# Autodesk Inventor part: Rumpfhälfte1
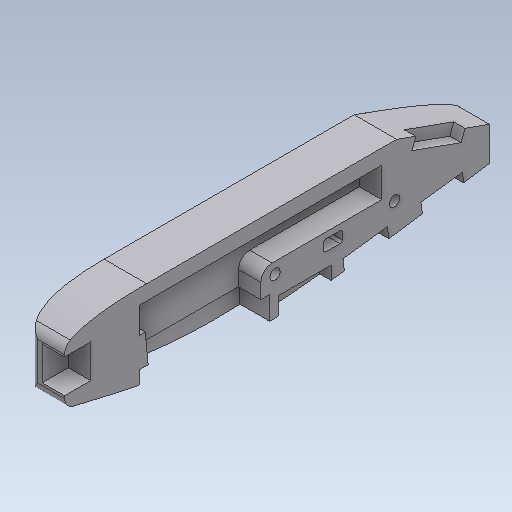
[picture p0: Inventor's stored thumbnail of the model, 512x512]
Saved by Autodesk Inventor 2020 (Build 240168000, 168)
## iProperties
Part Number: Rumpfhälfte1
Material: GEDA Polyamid schwarz
Document SubType Name: Modeling
Designer: Admin
Mass: 2170.29 g
Surface Area: 2080.02 cm^2
Volume: 1903.76 cm^3
Density: 1.14 g/cm^3
Appearance: GEDA Plastik schwarz A
Gewicht: 2,170 kg
G_L: 0
G_H: 0
G_B: 0
InventorVersion: 2019.4
VAULT_Status: in Bearbeitung
Revision: -
Max. Breite: 0
Max. Höhe: 0
Max. Länge: 0
Max. Abmessungen: 0 x 0 x 0
Author: Admin
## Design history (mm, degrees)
derived "RUMPFHÄLFTE_RUMPFHÄLFTE--IPT.ipt"
  sketch "Skizze1"
    geometry: L1 (0, 285)-(57, 285) reference; L2 (57, 285)-(57, -285) reference; L3 (57, -285)-(0, -285) reference; L4 (0, -285)-(0, 285) reference; L5 (40, 285)-(57, 285) reference; L6 (57, 285)-(57, 175) reference; L7 (36, -285)-(57, -285) reference; L8 (57, -285)-(57, -175) reference; 2 further points
  sketch "Skizze2"
    geometry: L1 (90, 0)-(139.333, 200) reference; L2 (139.333, 200)-(139.333, 250) reference; L3 (139.333, 250)-(90, 570) reference; L4 (0, 570)-(0, 0) reference; L5 (90, 0)-(137, 0) reference; L6 (137, 0)-(137, 570) reference; L7 (137, 570)-(90, 570) reference; L8 (45, 570)-(0, 445) reference; L9 (0, 570)-(0, 0) reference; L10 (20, 0)-(0, 20) reference; L11 (0, 20)-(0, 110) reference; L12 (46.491, 0)-(-10, 0) reference; L13 (-10, 0)-(-10, 570) reference; L14 (-10, 570)-(45, 570) reference; L15 (0, 110)-(0, 445) reference; L16 (0, 0)-(127, 0) reference; 7 further points
    constraints: 2 other
  sketch "Skizze3"
    geometry: L1 (27.484, -110)-(78.236, -110) reference; L2 (75, -110)-(30, -110) reference; L3 (30, -110)-(30, -75) reference; L4 (30, -75)-(75, -75) reference; L5 (75, -75)-(75, -110) reference; L6 (0, 335)-(0, 0) reference; L7 (0, 335)-(44.762, 459.339) reference; L8 (23.31, 355.465)-(47.02, 421.327) reference; L9 (32.907, 426.408)-(47.02, 421.327) reference; L10 (23.31, 355.465)-(9.196, 360.546) reference; L11 (5.4, 350)-(0, 335) reference; L12 (9.196, 360.546)-(32.907, 426.408) reference; L13 (127, -10)-(20, -10) reference; L14 (20, -10)-(20, 165) reference; L15 (127, 165)-(127, -10) reference; L16 (20, 165)-(60, 165) reference; L17 (60, 165)-(60, 315) reference; L18 (20, 315)-(20, 165) reference; L19 (127, 177)-(102, 177) reference; L20 (102, 177)-(102, 247) reference; L21 (102, 247)-(127, 247) reference; L22 (127, 247)-(127, 177) reference; L23 (45.703, 460)-(89.142, 460) reference; L24 (60, 315)-(20, 315) reference; L25 (95, -10)-(55, -10) reference; L26 (55, -10)-(55, -2) reference; L27 (55, -2)-(95, 2) reference; L28 (95, 2)-(95, -10) reference; L29 (60, 165)-(60, 153) reference; L30 (60, 153)-(95, 153) reference; L31 (95, 153)-(95, 165) reference; L32 (20, 165)-(60, 165) reference; L33 (95, 165)-(127, 165) reference; L34 (117.65, 264.922)-(102.65, 263) reference; L35 (102.65, 263)-(95.026, 322.514) reference; L36 (95.026, 322.514)-(110.026, 324.435) reference; L37 (103.659, 369.358)-(89.261, 367.514) reference; L38 (89.261, 367.514)-(82.146, 423.06) reference; L39 (82.146, 423.06)-(95.397, 424.757) reference; L40 (83, 237)-(68, 237) reference; L41 (68, 237)-(68, 262) reference; L42 (68, 262)-(83, 262) reference; L43 (83, 262)-(83, 237) reference; C1 r 7 at (75, 172) reference; C2 r 7 at (70, 332) reference; 7 further points
  sketch "Skizze4"
    geometry: L1 (-45.703, 460)-(-89.142, 460) reference; L2 (-71.2, 404.5)-(-60.5, 404.5) reference; L3 (-73, 389.5)-(-59.7, 389.5) reference; L4 (-75.1, 374.5)-(-58.7, 374.5) reference; L5 (-77.8, 359.5)-(-58.3, 359.5) reference; L6 (-79.5, 344.5)-(-57.7, 344.5) reference; L7 (-81.9, 329.5)-(-57.2, 329.5) reference; L8 (-83.6, 314.5)-(-56.7, 314.5) reference; L9 (-85.7, 299.5)-(-55.7, 299.5) reference; L10 (-87.8, 284.5)-(-55.1, 284.5) reference; L11 (-89.5, 269.5)-(-54.8, 269.5) reference; L12 (-91.7, 254.5)-(-54.8, 254.5) reference; L13 (-92.6, 239.5)-(-54.1, 239.5) reference; L14 (-94.1, 224.5)-(-54.1, 224.5) reference; L15 (-94.9, 209.5)-(-53.7, 209.5) reference; L16 (-96, 194.5)-(-53.5, 194.5) reference; L17 (-96.2, 179.5)-(-53.5, 179.5) reference; L18 (-96.2, 164.5)-(-53.8, 164.5) reference; L19 (-95.5, 149.5)-(-53.8, 149.5) reference; L20 (-94.7, 134.5)-(-54.2, 134.5) reference; L21 (-93.1, 119.5)-(-54.5, 119.5) reference; L22 (-90.2, 104.5)-(-55.3, 104.5) reference; L23 (-86.7, 89.5)-(-57.5, 89.5) reference; L24 (-80.3, 74.5)-(-58.9, 74.5) reference; L25 (-60.5, 403.36)-(-70.5, 407) reference; L26 (-70.5, 407)-(-67.5, 407) reference; L27 (-70.5, 407)-(-83.6, 314.5) reference; L28 (-83.6, 314.5)-(-100.2, 212) reference; L29 (-100.2, 212)-(-100.2, 137) reference; L30 (-100.2, 137)-(-87.5, 77) reference; L31 (-87.5, 77)-(-69.5, 60.5) reference; L32 (-65.5, 60.5)-(-55.5, 67) reference; L33 (-55.5, 67)-(-52.9, 149.5) reference; L34 (-52.9, 149.5)-(-52.9, 212) reference; L35 (-52.9, 212)-(-55.7, 299.5) reference; L36 (-55.7, 299.5)-(-60.5, 403.36) reference; C1 r 7 at (-70, 332) reference; C2 r 7 at (-75, 172) reference; A1 r 2.5 centre (-67.5, 62) between (-69.5, 60.5) and (-65.5, 60.5) reference; 2 further points; 1 other entity
    constraints: 1 other
feature "Volumenkörper1::RUMPFHÄLFTE_RUMPFHÄLFTE--IPT.ipt" dims "d0" = 10
tag "Bezeichnung1"
node "Volumenkörper1"
other parameters: "Gewicht" = 21.70291 [user parameter], "G_L" = 0 [user parameter], "G_H" = 0 [user parameter], "G_B" = 0 [user parameter], "Gewicht_1" = 21.70291, "G_L_1" = 0, "G_H_1" = 0, "G_B_1" = 0
